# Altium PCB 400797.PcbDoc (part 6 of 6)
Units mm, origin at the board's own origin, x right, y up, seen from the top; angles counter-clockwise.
Board outline 155 x 63.5 mm, 4 copper layers (Top Layer, Mid-Layer 1, Mid-Layer 2, Bottom Layer), stack 1.514 mm thick; 317 components, 286 nets, 1519 pads, 2174 vias.
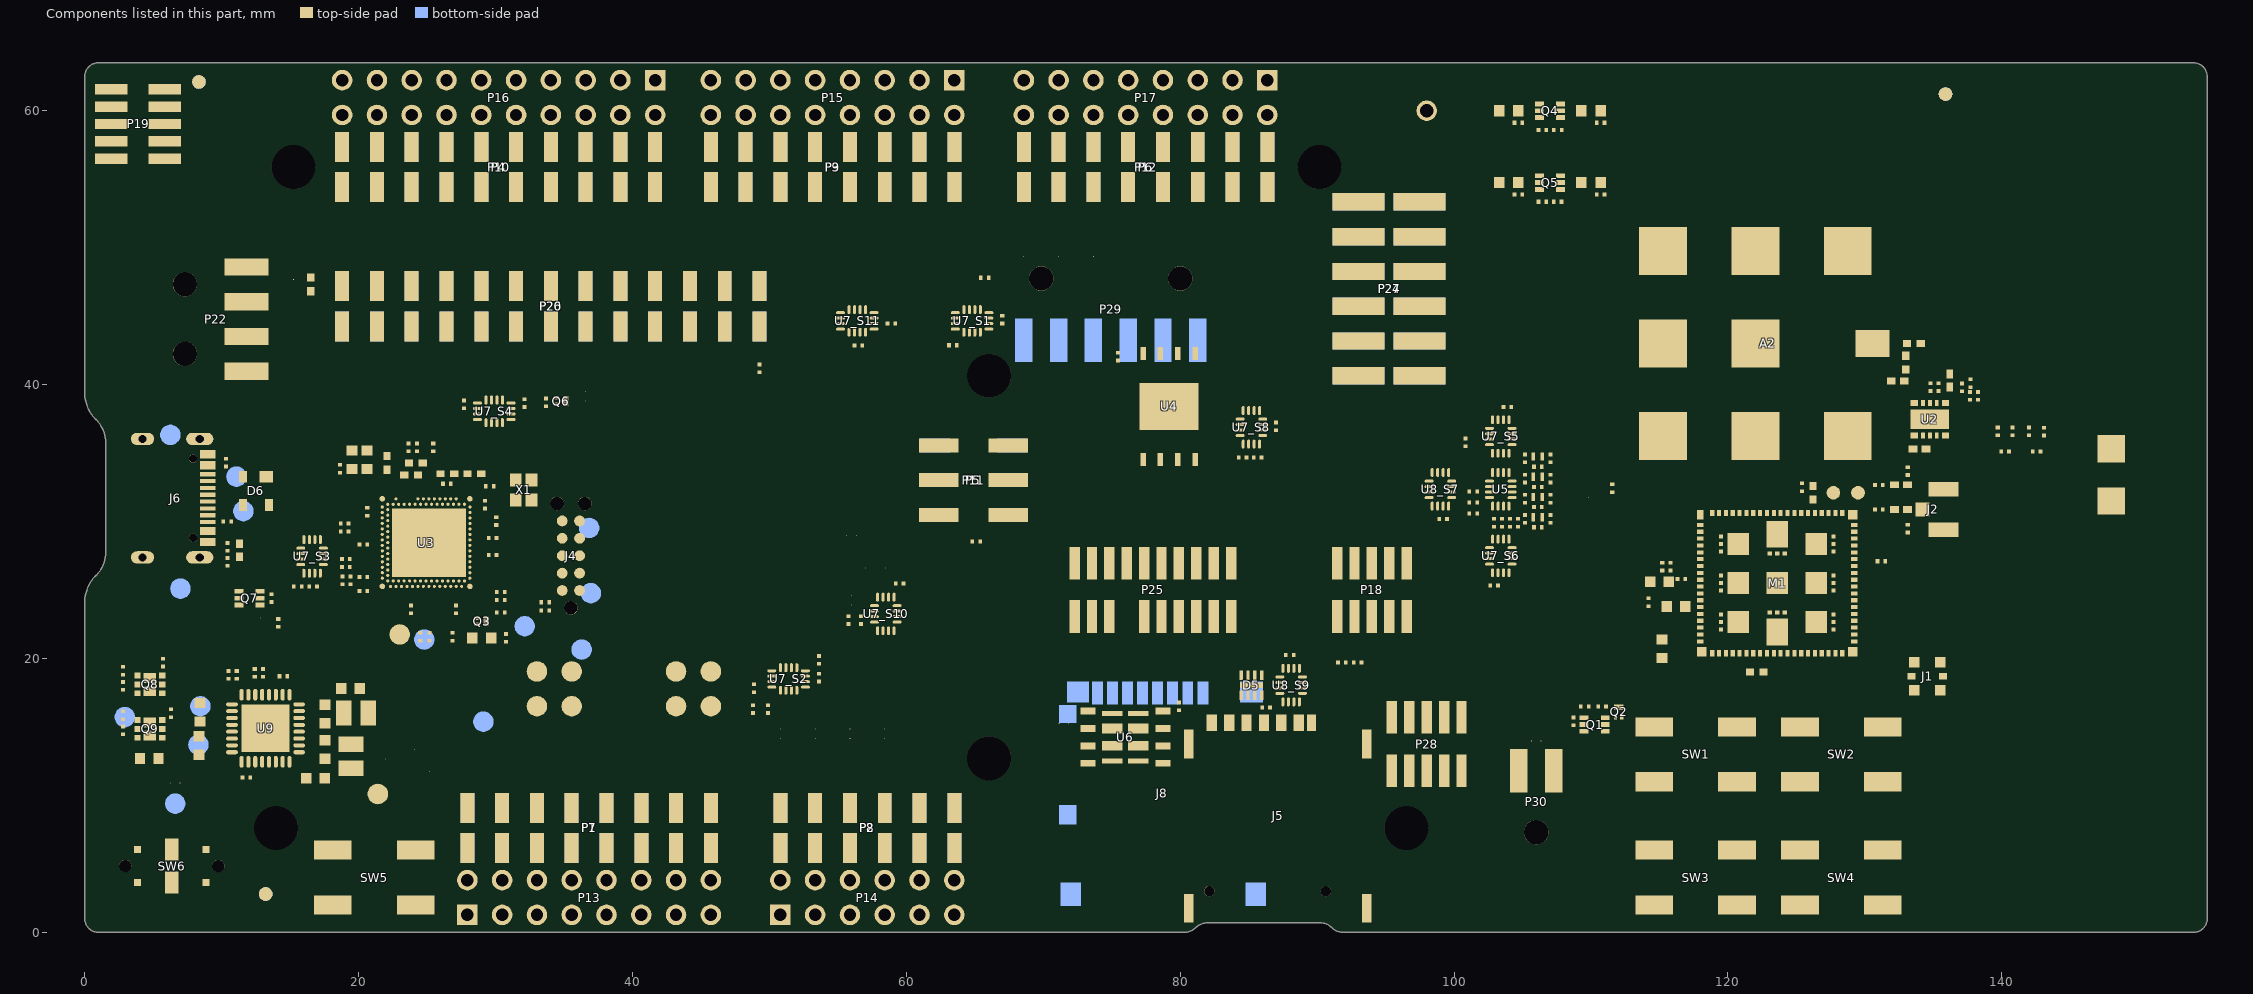
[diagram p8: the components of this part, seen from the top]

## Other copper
Top Layer:
  rectangle net GND: 141.732,30.087 142.85,34.416
  rectangle net GND: 141.732,36.867 142.85,38.837
  region net VIN_5V': 39.626,46.225 38.606,46.225 38.606,45.225 39.626,45.225
  region net VDD_nRF: 42.166,46.225 41.146,46.225 41.146,45.225 42.166,45.225
  region net VDD_nRF: 111.048,31.745 111.05,31.747 111.05,31.89 cw(c111.256,31.89) 111.11,32.035 111.307,32.232 cw(c111.41,32.129) 111.41,32.275 111.679,32.275 cw(c111.679,32.104) 111.8,32.225 112.007,32.018 cw(c111.906,31.916) 112.049,31.916 112.049,31.742
  region net VDD_5V: 43.446,42.581 44.946,42.581 cw(c44.946,42.256) 45.271,42.256 cw(c44.946,42.256) 44.946,41.931 43.446,41.931 cw(c43.446,42.256) 43.121,42.256 cw(c43.446,42.256)
  region net VDD: 71.375,20.85 70.5,20.85 ccw(c70.5,20.35) 70,20.35 ccw(c70.5,20.35) 70.5,19.85 71.375,19.85
  region net VDD: 71.125,20.85 72,20.85 cw(c72,20.35) 72.5,20.35 cw(c72,20.35) 72,19.85 71.125,19.85
  region net VDD: 22.558,39.485 23.177,38.866 ccw(c23.53,39.22) 23.884,38.866 ccw(c23.53,39.22) 23.884,39.573 23.265,40.192
  region net VDD: 22.735,39.308 22.116,39.927 cw(c22.47,40.28) 22.116,40.634 cw(c22.47,40.28) 22.823,40.634 23.442,40.015
  region net VDD_5V: 16.144,38.66 16.144,36.749 cw(c15.819,36.751) 15.494,36.751 15.494,38.66 cw(c15.819,38.66) 15.819,38.985 cw(c15.819,38.66)
  region net VIN_5V': 3.62,15.29 3.62,16.195 cw(c4,16.195) 4,16.575 5.5,16.575 cw(c5.5,16.25) 5.825,16.25 cw(c5.5,16.25) 5.5,15.925 4.285,15.925 ccw(c4.285,15.71) 4.07,15.71 4.07,15.29
  region net GND: 18.025,10.85 17.25,10.85 17.25,11.425 16.825,11.85 16.3,11.85 16.2,11.95 16.2,13.275 15.975,13.5 15.65,13.5 15.65,13.8 16.175,13.8 16.925,13.05 18.025,13.05
  region net GND: 15.65,15.5 16.2,15.5 16.95,16.25 18.025,16.25 18.025,17.025 18.4,17.4 19.1,17.4 19.1,18.2 17.5,18.2 17.15,17.85 17.15,16.975 15.975,15.8 15.65,15.8
  pour cut-out: 16.201,16.024 17.138,16.962 17.05,17.05 16.113,16.113
  pour cut-out: 17.025,17.85 17.025,17 17.15,17 17.15,17.85
  pour cut-out: 17.163,17.862 17.513,18.212 17.425,18.3 17.075,17.95
  pour cut-out: 19.1,18.325 17.5,18.325 17.5,18.2 19.1,18.2
  pour cut-out: 140.004,36.799 140.075,36.752 140.138,36.739 140.269,36.652 140.356,36.521 140.387,36.367 140.387,35.867 140.356,35.713 140.292,35.617 140.309,35.591 140.368,35.552 140.456,35.421 140.486,35.267 140.486,34.967 140.456,34.813 140.368,34.682 140.31,34.643 140.269,34.582 140.138,34.495 139.984,34.464 139.384,34.464 139.23,34.495 139.099,34.582 139.012,34.713 138.982,34.867 138.982,35.367 139.012,35.521 139.074,35.614 138.984,35.614 138.864,35.638 138.76,35.595 138.667,35.524 138.596,35.431 138.551,35.323 138.531,35.171 138.531,20.319 138.535,20.3 138.531,20.28 138.533,20.261 138.501,19.938 138.49,19.9 138.486,19.861 138.392,19.551 138.373,19.516 138.362,19.478 138.209,19.193 138.184,19.162 138.165,19.127 137.96,18.877 137.929,18.851 137.904,18.821 137.654,18.615 137.619,18.597 137.588,18.572 137.303,18.419 137.265,18.407 137.23,18.389 136.92,18.295 136.88,18.291 136.842,18.279 136.52,18.248 136.5,18.249 136.481,18.246 136.461,18.249 136.345,18.249 136.288,18.165 136.158,18.078 136.004,18.047 135.424,18.047 135.27,18.078 135.139,18.165 135.052,18.296 135.021,18.45 135.021,18.95 135.052,19.104 135.139,19.235 135.27,19.322 135.424,19.353 136.004,19.353 136.158,19.322 136.288,19.235 136.336,19.163 136.449,19.163 136.702,19.188 136.915,19.252 137.111,19.357 137.282,19.498 137.423,19.67 137.528,19.866 137.593,20.079 137.618,20.332 137.618,35.186 137.613,35.207 137.619,35.233 137.617,35.26 137.65,35.51 137.667,35.56 137.677,35.612 137.774,35.845 137.803,35.889 137.826,35.936 137.98,36.137 138.02,36.172 138.055,36.211 138.255,36.365 138.302,36.388 138.346,36.418 138.58,36.514 138.631,36.525 138.681,36.542 138.778,36.554 138.83,36.589 138.984,36.62 139.078,36.62 139.099,36.652 139.23,36.739 139.338,36.761 139.396,36.799 139.55,36.83 139.85,36.83
  pour cut-out: 30.6,22 30.1,22 30.1,21 30.6,21
  pour cut-out: 29.2,22 28.7,22 28.7,21 29.2,21
  region net VSYS: 16.613,14.511 17.229,13.895 17.229,13.7 17.938,13.7 17.938,15.6 17.229,15.6 17.229,15.427 16.613,14.811
  pour cut-out: 19.6,18.3 19.1,18.3 19.1,17.3 19.6,17.3
  pour cut-out: 8.7,13.4 8.7,13.9 7.7,13.9 7.7,13.4
  region net 5V: 38.61,3.811 38.61,10.2 37.59,10.2 37.59,3.811
  region net VDD_5V: 8,13.95 8,14.8 6.45,14.8 6.05,14.4 5.4,14.4 5.4,13.95
  region net VDD_5V: 6.4,11.4 6.1,11.4 5.9,11.6 5.9,14.4 5.4,14.4 5.4,13.8 5.1,13.8 5.1,10.7 5.4,10.4 6.4,10.4
  region net VBUS': 10.3,26.9 11,26.9 11,27.7 11.6,27.7 11.6,26.7 11.2,26.3 10.3,26.3
  region net VDD_5V: 7.9,14.8 7.9,13.95 9.45,13.95 10,14.5 10.75,14.5 10.75,14.8
  region net VSYS: 7.95,15 7.95,15.95 9.75,15.95 10.4,15.3 10.8,15.3 10.8,15
  pour cut-out: 20.664,12.575 20.664,15.015 18.575,15.015 18.575,12.575
  region net VDD_3V0: 20.1,15.058 20.1,16.893 19.675,17.318 19.675,18.293 20.45,18.293 21.2,17.542 21.2,15.058
  region net VDD_1V8: 18.175,10.6 17.1,10.6 16.9,10.8 16.904,10.804 16.904,11.396 16.65,11.65 15.9,11.65 15.9,10.5 16.25,10.15 19.643,10.15 20.41,10.917 20.41,12.575 18.575,12.575 18.575,11
  pour cut-out: 126.154,20.972 126.285,20.885 126.372,20.754 126.403,20.6 126.403,20.15 126.372,19.996 126.356,19.972 126.356,19.718 126.369,19.614 126.404,19.531 126.469,19.446 126.634,19.319 126.842,19.233 127.058,19.204 127.066,19.206 132.8,19.206 132.819,19.235 132.95,19.322 133.104,19.353 133.684,19.353 133.838,19.322 133.968,19.235 134.056,19.104 134.086,18.95 134.086,18.45 134.056,18.296 133.968,18.165 133.838,18.078 133.684,18.047 133.104,18.047 132.95,18.078 132.819,18.165 132.8,18.194 127.09,18.194 127.066,18.189 127.04,18.195 127.013,18.193 126.632,18.243 126.582,18.26 126.53,18.27 126.175,18.418 126.131,18.447 126.084,18.47 125.779,18.704 125.761,18.724 125.739,18.739 125.715,18.775 125.707,18.782 125.684,18.812 125.675,18.822 125.674,18.825 125.555,18.98 125.532,19.027 125.503,19.071 125.407,19.302 125.397,19.353 125.38,19.403 125.347,19.651 125.349,19.677 125.344,19.703 125.344,19.705 125.344,19.972 125.328,19.996 125.297,20.15 125.297,20.6 125.328,20.754 125.415,20.885 125.546,20.972 125.7,21.003 126,21.003
  pour cut-out: 133.434,29.702 133.565,29.615 133.652,29.484 133.683,29.33 133.683,29.06 133.652,28.906 133.643,28.892 133.643,28.132 133.642,28.131 133.642,22.85 133.638,22.83 133.64,22.811 133.607,22.478 133.596,22.44 133.592,22.401 133.495,22.081 133.476,22.046 133.465,22.008 133.308,21.714 133.282,21.683 133.264,21.648 133.052,21.39 133.021,21.365 132.996,21.334 132.738,21.122 132.703,21.104 132.672,21.078 132.378,20.921 132.34,20.91 132.305,20.891 131.985,20.794 131.946,20.79 131.908,20.779 131.575,20.746 131.556,20.748 131.536,20.744 129.628,20.744 129.604,20.728 129.45,20.697 129,20.697 128.846,20.728 128.715,20.815 128.628,20.946 128.597,21.1 128.597,21.4 128.628,21.554 128.715,21.685 128.846,21.772 129,21.803 129.45,21.803 129.604,21.772 129.609,21.769 131.536,21.769 131.539,21.768 131.747,21.789 131.95,21.85 132.137,21.95 132.301,22.085 132.436,22.249 132.536,22.436 132.597,22.639 132.618,22.847 132.617,22.85 132.617,28.131 132.617,28.132 132.617,28.892 132.608,28.906 132.577,29.06 132.577,29.33 132.608,29.484 132.695,29.615 132.826,29.702 132.98,29.733 133.28,29.733
  region net VDD_5V: 44.706,47.075 44.706,42.956 45.222,42.44 43.17,42.44 43.686,42.956 43.686,47.075
  pour cut-out: 30.792,34.199 30.792,30.466 33.104,30.466 33.104,34.199
  pour cut-out: 134.507,1.667 142.284,1.667 142.284,0.001 134.507,0.001
Mid-Layer 1:
  pour cut-out: 131.28,31.205 132.395,31.205 cw(c132.395,31.045) 132.555,31.045 132.555,30.73 cw(c132.38,30.73) 132.38,30.555 131.295,30.555 cw(c131.295,30.747) 131.102,30.748 131.102,31.027 cw(c131.28,31.027)
  pour cut-out: 7.225,11.175 7.225,10.625 cw(c6.875,10.625) 6.875,10.275 6.3,10.275 cw(c6.3,10.625) 5.95,10.625 5.95,11.175 cw(c6.3,11.175) 6.3,11.525 6.875,11.525 cw(c6.875,11.175)
  pour cut-out: 84.625,29.525 84.625,28.975 cw(c84.275,28.975) 84.275,28.625 83.7,28.625 cw(c83.7,28.975) 83.35,28.975 83.35,29.525 cw(c83.7,29.525) 83.7,29.875 84.275,29.875 cw(c84.275,29.525)
  pour cut-out: 72.125,15.525 72.125,14.975 cw(c71.775,14.975) 71.775,14.625 71.2,14.625 cw(c71.2,14.975) 70.85,14.975 70.85,15.525 cw(c71.2,15.525) 71.2,15.875 71.775,15.875 cw(c71.775,15.525)
  pour cut-out: 72.125,13.525 72.125,12.975 cw(c71.775,12.975) 71.775,12.625 71.2,12.625 cw(c71.2,12.975) 70.85,12.975 70.85,13.525 cw(c71.2,13.525) 71.2,13.875 71.775,13.875 cw(c71.775,13.525)
  pour cut-out: 106.625,14.25 106.625,13.7 cw(c106.275,13.7) 106.275,13.35 105.7,13.35 cw(c105.7,13.7) 105.35,13.7 105.35,14.25 cw(c105.7,14.25) 105.7,14.6 106.275,14.6 cw(c106.275,14.25)
  pour cut-out: 56.275,29.856 55.725,29.856 cw(c55.725,30.206) 55.375,30.206 55.375,30.781 cw(c55.725,30.781) 55.725,31.131 56.275,31.131 cw(c56.275,30.781) 56.625,30.781 56.625,30.206 cw(c56.275,30.206)
  pour cut-out: 56.625,32.256 56.625,31.706 cw(c56.275,31.706) 56.275,31.356 55.7,31.356 cw(c55.7,31.706) 55.35,31.706 55.35,32.256 cw(c55.7,32.256) 55.7,32.606 56.275,32.606 cw(c56.275,32.256)
  pour cut-out: 56.625,29.256 56.625,28.706 cw(c56.275,28.706) 56.275,28.356 55.7,28.356 cw(c55.7,28.706) 55.35,28.706 55.35,29.256 cw(c55.7,29.256) 55.7,29.606 56.275,29.606 cw(c56.275,29.256)
  pour cut-out: 67.625,26.525 67.625,25.975 cw(c67.275,25.975) 67.275,25.625 66.7,25.625 cw(c66.7,25.975) 66.35,25.975 66.35,26.525 cw(c66.7,26.525) 66.7,26.875 67.275,26.875 cw(c67.275,26.525)
  pour cut-out: 67.625,28.025 67.625,27.475 cw(c67.275,27.475) 67.275,27.125 66.7,27.125 cw(c66.7,27.475) 66.35,27.475 66.35,28.025 cw(c66.7,28.025) 66.7,28.375 67.275,28.375 cw(c67.275,28.025)
  pour cut-out: 58.775,25.625 58.225,25.625 cw(c58.225,25.975) 57.875,25.975 57.875,26.55 cw(c58.225,26.55) 58.225,26.9 58.775,26.9 cw(c58.775,26.55) 59.125,26.55 59.125,25.975 cw(c58.775,25.975)
  pour cut-out: 57.275,25.625 56.725,25.625 cw(c56.725,25.975) 56.375,25.975 56.375,26.55 cw(c56.725,26.55) 56.725,26.9 57.275,26.9 cw(c57.275,26.55) 57.625,26.55 57.625,25.975 cw(c57.275,25.975)
  pour cut-out: 56.275,23.625 55.725,23.625 cw(c55.725,23.975) 55.375,23.975 55.375,24.55 cw(c55.725,24.55) 55.725,24.9 56.275,24.9 cw(c56.275,24.55) 56.625,24.55 56.625,23.975 cw(c56.275,23.975)
  pour cut-out: 58.725,20.875 59.275,20.875 cw(c59.275,20.525) 59.625,20.525 59.625,19.95 cw(c59.275,19.95) 59.275,19.6 58.725,19.6 cw(c58.725,19.95) 58.375,19.95 58.375,20.525 cw(c58.725,20.525)
  pour cut-out: 57.775,19.625 57.225,19.625 cw(c57.225,19.975) 56.875,19.975 56.875,20.55 cw(c57.225,20.55) 57.225,20.9 57.775,20.9 cw(c57.775,20.55) 58.125,20.55 58.125,19.975 cw(c57.775,19.975)
  pour cut-out: 58.145,15.125 58.695,15.125 cw(c58.695,14.775) 59.045,14.775 59.045,14.2 cw(c58.695,14.2) 58.695,13.85 58.145,13.85 cw(c58.145,14.2) 57.795,14.2 57.795,14.775 cw(c58.145,14.775)
  pour cut-out: 56.155,13.875 55.605,13.875 cw(c55.605,14.225) 55.255,14.225 55.255,14.8 cw(c55.605,14.8) 55.605,15.15 56.155,15.15 cw(c56.155,14.8) 56.505,14.8 56.505,14.225 cw(c56.155,14.225)
  pour cut-out: 53.065,15.125 53.615,15.125 cw(c53.615,14.775) 53.965,14.775 53.965,14.2 cw(c53.615,14.2) 53.615,13.85 53.065,13.85 cw(c53.065,14.2) 52.715,14.2 52.715,14.775 cw(c53.065,14.775)
  pour cut-out: 51.075,13.875 50.525,13.875 cw(c50.525,14.225) 50.175,14.225 50.175,14.8 cw(c50.525,14.8) 50.525,15.15 51.075,15.15 cw(c51.075,14.8) 51.425,14.8 51.425,14.225 cw(c51.075,14.225)
  pour cut-out: 24.925,12.725 25.475,12.725 cw(c25.475,12.375) 25.825,12.375 25.825,11.8 cw(c25.475,11.8) 25.475,11.45 24.925,11.45 cw(c24.925,11.8) 24.575,11.8 24.575,12.375 cw(c24.925,12.375)
  pour cut-out: 23.475,13.425 23.475,13.975 cw(c23.825,13.975) 23.825,14.325 24.4,14.325 cw(c24.4,13.975) 24.75,13.975 24.75,13.425 cw(c24.4,13.425) 24.4,13.075 23.825,13.075 cw(c23.825,13.425)
  pour cut-out: 22.325,12.675 22.325,12.125 cw(c21.975,12.125) 21.975,11.775 21.4,11.775 cw(c21.4,12.125) 21.05,12.125 21.05,12.675 cw(c21.4,12.675) 21.4,13.025 21.975,13.025 cw(c21.975,12.675)
  pour cut-out: 9.125,56.975 9.125,57.525 cw(c9.475,57.525) 9.475,57.875 10.05,57.875 cw(c10.05,57.525) 10.4,57.525 10.4,56.975 cw(c10.05,56.975) 10.05,56.625 9.475,56.625 cw(c9.475,56.975)
  pour cut-out: 9.125,58.82 9.125,59.37 cw(c9.475,59.37) 9.475,59.72 10.05,59.72 cw(c10.05,59.37) 10.4,59.37 10.4,58.82 cw(c10.05,58.82) 10.05,58.47 9.475,58.47 cw(c9.475,58.82)
  pour cut-out: 15.515,46.694 14.965,46.694 cw(c14.965,47.044) 14.615,47.044 14.615,47.619 cw(c14.965,47.619) 14.965,47.969 15.515,47.969 cw(c15.515,47.619) 15.865,47.619 15.865,47.044 cw(c15.515,47.044)
  pour cut-out: 19.791,39.773 20.341,39.773 cw(c20.341,39.423) 20.691,39.423 20.691,38.848 cw(c20.341,38.848) 20.341,38.498 19.791,38.498 cw(c19.791,38.848) 19.441,38.848 19.441,39.423 cw(c19.791,39.423)
  pour cut-out: 36.3,39.787 36.85,39.787 cw(c36.85,39.437) 37.2,39.437 37.2,38.862 cw(c36.85,38.862) 36.85,38.512 36.3,38.512 cw(c36.3,38.862) 35.95,38.862 35.95,39.438 cw(c36.3,39.438)
  pour cut-out: 73.935,41.58 73.385,41.58 cw(c73.385,41.93) 73.035,41.93 73.035,42.505 cw(c73.385,42.505) 73.385,42.855 73.935,42.855 cw(c73.935,42.505) 74.285,42.505 74.285,41.93 cw(c73.935,41.93)
  pour cut-out: 73.385,49.625 73.935,49.625 cw(c73.935,49.275) 74.285,49.275 74.285,48.7 cw(c73.935,48.7) 73.935,48.35 73.385,48.35 cw(c73.385,48.7) 73.035,48.7 73.035,49.275 cw(c73.385,49.275)
  pour cut-out: 70.845,49.625 71.395,49.625 cw(c71.395,49.275) 71.745,49.275 71.745,48.7 cw(c71.395,48.7) 71.395,48.35 70.845,48.35 cw(c70.845,48.7) 70.495,48.7 70.495,49.275 cw(c70.845,49.275)
  pour cut-out: 68.305,49.625 68.855,49.625 cw(c68.855,49.275) 69.205,49.275 69.205,48.7 cw(c68.855,48.7) 68.855,48.35 68.305,48.35 cw(c68.305,48.7) 67.955,48.7 67.955,49.275 cw(c68.305,49.275)
  pour cut-out: 104.098,51.076 104.098,50.526 cw(c103.748,50.526) 103.748,50.176 103.173,50.176 cw(c103.173,50.526) 102.823,50.526 102.823,51.076 cw(c103.172,51.076) 103.173,51.426 103.748,51.426 cw(c103.748,51.076)
  pour cut-out: 110.075,28.563 109.525,28.563 cw(c109.525,28.913) 109.175,28.913 109.175,29.488 cw(c109.525,29.488) 109.525,29.838 110.075,29.838 cw(c110.075,29.488) 110.425,29.488 110.425,28.912 cw(c110.075,28.912)
  pour cut-out: 110.075,30.75 109.525,30.75 cw(c109.525,31.1) 109.175,31.1 109.175,31.675 cw(c109.525,31.675) 109.525,32.025 110.075,32.025 cw(c110.075,31.675) 110.425,31.675 110.425,31.1 cw(c110.075,31.1)
  pour cut-out: 135.647,36.572 136.128,36.572 cw(c136.128,36.475) 136.225,36.475 136.225,36.075 cw(c136.122,36.075) 136.122,35.972 135.653,35.972 cw(c135.653,36.075) 135.55,36.075 135.55,36.475 cw(c135.647,36.475)
  pour cut-out: 134.175,35.625 134.775,35.625 cw(c134.775,35.525) 134.875,35.525 134.875,35.075 cw(c134.775,35.075) 134.775,34.975 134.175,34.975 cw(c134.175,35.075) 134.075,35.075 134.075,35.525 cw(c134.175,35.525)
  pour cut-out: 133.225,35.625 133.825,35.625 cw(c133.825,35.525) 133.925,35.525 133.925,35.075 cw(c133.825,35.075) 133.825,34.975 133.225,34.975 cw(c133.225,35.075) 133.125,35.075 133.125,35.525 cw(c133.225,35.525)
  pour cut-out: 133.787,18.357 133,18.357 133,19.043 133.787,19.043
  pour cut-out: 135,17.301 134.1,17.306 134.1,18.1 133.1,18.1 133.103,19.3 134.1,19.3 134.1,20.1 135,20.1 135,19.3 136,19.3 136,18.1 135,18.1
  pour cut-out: 135.32,19.043 136.107,19.043 136.107,18.357 135.32,18.357
  pour cut-out: 11.825,21.6 11.825,23.6 13.825,23.6 13.825,21.6
  pour cut-out: 133.3,39.925 132.5,39.925 132.5,40.575 133.3,40.575
  pour cut-out: 133.325,41.5 133.325,40.7 132.675,40.7 132.675,41.5
  pour cut-out: 133.325,42.5 133.325,41.7 132.675,41.7 132.675,42.5
  pour cut-out: 133.5,42.675 132.7,42.675 132.7,43.325 133.5,43.325
  pour cut-out: 133.264,38.947 133.939,38.947 133.939,38.347 133.264,38.347
  pour cut-out: 133.505,31.555 137.03,31.555 137.03,30.23 133.505,30.23
  pour cut-out: 131.102,33.005 132.555,33.005 132.555,32.355 131.102,32.355
  pour cut-out: 132.705,33.005 133.505,33.005 133.505,32.355 132.705,32.355
  pour cut-out: 132.705,31.205 133.505,31.205 133.505,30.555 132.705,30.555
  pour cut-out: 133.355,29.978 133.355,29.553 132.905,29.553 132.905,29.978
  pour cut-out: 133.355,29.408 133.355,28.983 132.905,28.983 132.905,29.408
  pour cut-out: 132.905,33.753 132.905,34.178 133.355,34.178 133.355,33.753
  pour cut-out: 132.905,33.183 132.905,33.608 133.355,33.608 133.355,33.183
  pour cut-out: 134.507,1.667 142.284,1.667 142.284,0.001 134.507,0.001
Mid-Layer 2:
  region net VDD_nRF: 111,32.2 112.1,32.2 cw(c112.1,32) 112.3,32 112.3,31.4 110.8,31.4 110.8,32 cw(c111,32)
  region net VDD_5V: 15.494,36.75 15.494,38.25 cw(c15.819,38.25) 15.819,38.575 cw(c15.819,38.25) 16.144,38.25 16.144,36.75 cw(c15.819,36.75) 15.819,36.425 cw(c15.819,36.75)
  region net VIN_5V': 38.791,44.221 38.791,45.721 cw(c39.116,45.721) 39.116,46.046 cw(c39.116,45.721) 39.441,45.721 39.441,44.221 cw(c39.116,44.221) 39.116,43.896 cw(c39.116,44.221)
  region net VDD_5V: 43.446,42.581 44.946,42.581 cw(c44.946,42.256) 45.271,42.256 cw(c44.946,42.256) 44.946,41.931 43.446,41.931 cw(c43.446,42.256) 43.121,42.256 cw(c43.446,42.256)
  region net VDD: 23.301,38.99 22.24,40.051 cw(c22.47,40.28) 22.24,40.51 cw(c22.47,40.28) 22.699,40.51 23.76,39.449 cw(c23.53,39.22) 23.76,38.99 cw(c23.53,39.22)
  region net VDD: 71.375,20.85 70.5,20.85 ccw(c70.5,20.35) 70,20.35 ccw(c70.5,20.35) 70.5,19.85 71.375,19.85
  region net VDD: 71.125,20.85 72,20.85 cw(c72,20.35) 72.5,20.35 cw(c72,20.35) 72,19.85 71.125,19.85
  region net 5V: 66.972,35.236 68.472,35.236 ccw(c68.472,35.561) 68.797,35.561 ccw(c68.472,35.561) 68.472,35.886 66.972,35.886 ccw(c66.972,35.561) 66.647,35.561 ccw(c66.972,35.561)
  region net VIN_5V': 14.719,36.75 14.719,38.25 cw(c15.044,38.25) 15.044,38.575 cw(c15.044,38.25) 15.369,38.25 15.369,36.75 cw(c15.044,36.75) 15.044,36.425 cw(c15.044,36.75)
  region net VDD: 22.411,38.439 22.723,38.752 cw(c23.068,38.406) 23.068,38.895 23.595,38.895 22.145,40.345 22.145,39.793 cw(c21.717,39.793) 22.019,39.491 21.689,39.161
  pour cut-out: 134.507,1.667 142.284,1.667 142.284,0.001 134.507,0.001
Bottom Layer:
  rectangle net GND: 141.834,30.325 142.951,38.812
  rectangle net VIN_5V': 38.606,45.225 39.626,46.225
  rectangle net VDD_nRF: 41.146,45.225 42.166,46.225
  region net VDD_nRF: 112.1,31.3 111,31.3 cw(c111,31.5) 110.8,31.5 110.8,32.8 111.782,32.8 112.3,32.282 112.3,31.5 cw(c112.1,31.5)
  region net 5V: 55.425,20.5 55.425,22 cw(c55.75,22) 55.75,22.325 cw(c55.75,22) 56.075,22 56.075,20.5 cw(c55.75,20.5) 55.75,20.175 cw(c55.75,20.5)
  region net VDD_5V: 43.446,42.581 44.946,42.581 cw(c44.946,42.256) 45.271,42.256 cw(c44.946,42.256) 44.946,41.931 43.446,41.931 cw(c43.446,42.256) 43.121,42.256 cw(c43.446,42.256)
  region net VDD: 22.735,39.308 22.116,39.927 cw(c22.47,40.28) 22.116,40.634 cw(c22.47,40.28) 22.823,40.634 23.442,40.015
  region net VDD: 22.558,39.485 23.177,38.866 ccw(c23.53,39.22) 23.884,38.866 ccw(c23.53,39.22) 23.884,39.573 23.265,40.192
  region net VIN_5V': 14.719,36.75 14.719,38.25 cw(c15.044,38.25) 15.044,38.575 cw(c15.044,38.25) 15.369,38.25 15.369,36.75 cw(c15.044,36.75) 15.044,36.425 cw(c15.044,36.75)
  region net VDD_5V: 16.144,38.25 16.144,36.75 cw(c15.819,36.75) 15.819,36.425 cw(c15.819,36.75) 15.494,36.75 15.494,38.25 cw(c15.819,38.25) 15.819,38.575 cw(c15.819,38.25)
  region net VIN_5V': 4,16.575 5.5,16.575 cw(c5.5,16.25) 5.825,16.25 cw(c5.5,16.25) 5.5,15.925 4,15.925 cw(c4,16.25) 3.675,16.25 cw(c4,16.25)
  region net 5V: 37.59,3.811 37.59,9.3 38.61,9.3 38.61,3.811
  region net VSYS: 17.9,14.3 17.9,15.3 15.7,17.5 10.7,17.5 8.8,15.6 8.8,14.9 10.3,14.9 10.3,15.8 11.1,16.6 15.4,16.6 16.6,15.4 16.6,14.3
  region net VDD_5V: 43.686,47.075 43.686,42.956 43.17,42.44 45.222,42.44 44.706,42.956 44.706,47.075
  region: 147.207,48.236 147.207,48.998 147.735,48.998 147.735,48.236
  pour cut-out: 134.507,1.667 142.284,1.667 142.284,0.001 134.507,0.001
Multi-Layer:
  pour cut-out: 142.284,51.067 138.063,51.067 138.063,63.501 142.284,63.501

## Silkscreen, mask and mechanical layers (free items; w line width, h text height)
Top Overlay:
  circle w0.254: c88.113,54.367 r0.127
  circle w0.254: c65.278,54.357 r0.127
  circle w0.254: c43.434,54.357 r0.127
  circle w0.254: c26.162,9.145 r0.127
  circle w0.254: c49.022,9.145 r0.127
  region: 78.374,9.074 78.374,8.33 73.156,8.362 74.122,9.329 78.119,9.329
  region: 78.296,3.108 78.296,2.248 78.119,2.071 73.281,2.071 73.104,2.248 73.174,2.318 73.174,3.13 78.274,3.13
  lines w0.1: 9.7,19.5 7.6,19.5 7.6,10.7 20.4,10.7 ; 13.7,19.5 21.6,19.5 21.6,13.3 ; 21.6,11 21.6,11.4 ; 18.1,32.8 19.7,32.8 19.7,22.8 27.9,22.8 27.9,24.6 29.7,24.6 29.7,27 30.7,27 30.7,30.4 33.3,30.4 33.3,34.8 22.7,34.8 22.7,35.9 18.1,35.9 18.1,32.8
  lines w0.15: 37.084,17.78 41.656,17.78 ; 39.37,15.494 39.37,20.066 ; 37.084,15.494 37.084,20.066 41.656,20.066 41.656,15.494 37.084,15.494
  lines w0.25: 73.104,8.237 73.104,2.248 ccw(c73.281,2.248) 73.281,2.071 78.119,2.071 ccw(c78.119,2.248) 78.296,2.248 78.296,9.152 ccw(c78.119,9.152) 78.119,9.329 74.195,9.329 ; 73.155,8.362 74.07,9.277
  lines w0.254: 12.38,60.961 92.837,60.961 ; 14.224,62.231 17.018,62.231 ; 16.764,62.231 16.256,62.485 16.256,61.977 17.018,62.231 ; 26.67,2.541 67.996,2.541 ; 65.481,1.232 65.989,0.978 65.989,1.486 65.227,1.232 ; 68.021,1.232 65.227,1.232 ; 88.341,62.192 88.849,61.938 88.849,62.446 88.087,62.192 ; 90.881,62.192 88.087,62.192 ; 17.018,62.231 16.256,61.723 16.256,62.739 17.018,62.231 ; 65.227,1.232 65.989,0.724 65.989,1.74 65.227,1.232 ; 88.087,62.192 88.849,62.7 88.849,61.684 88.087,62.192
  text "'.PCBnumber'" at 138.776,61.712 h2.03
  text "GND" at 10.662,61.695 h1.78
  text "GND" at 91.198,61.656 h1.78
  text "'.PCBrevision'" at 138.855,60.492 h1.52
  text "GND" at 96.383,57.564 h1.78
  text "DEBUG OUT" at 0.418,53.688 h1.8
  text "'.Productname'" at 115.825,53.45 h3
  text "COEX1" at 99.601,52.949 h1.3
  text "COEX0" at 87.337,52.919 h1.3
  text "COEX2" at 87.421,50.484 h1.3
  text "P0.11" at 34.537,50.465 h1.7 r90
  text "P0.29" at 99.601,50.418 h1.3
  text "nRF CURRENT / MEASUREMENT" at 0.418,50.296 h1.8
  text "P0.21" at 86.861,50.189 h1.7 r90
  text "P0.31" at 19.297,50.168 h1.7 r90
  text "GND" at 26.928,50.111 h1.7 r90
  text "P0.12" at 31.997,50.096 h1.7 r90
  text "P0.01" at 61.461,50.076 h1.7 r90
  text "P0.13" at 29.457,50.066 h1.7 r90
  text "P0.10" at 37.077,49.986 h1.7 r90
  text "P0.27" at 71.621,49.856 h1.7 r90
  text "P0.22" at 84.321,49.82 h1.7 r90
  text "P0.25" at 76.701,49.774 h1.7 r90
  text "P0.23" at 81.781,49.79 h1.7 r90
  text "P0.28" at 69.081,49.756 h1.7 r90
  text "P0.26" at 74.161,49.747 h1.7 r90
  text "P0.07" at 46.221,49.743 h1.7 r90
  text "P0.24" at 79.241,49.741 h1.7 r90
  text "P0.20" at 24.377,49.71 h1.7 r90
  text "P0.02" at 58.921,49.707 h1.7 r90
  text "P0.30" at 21.837,49.689 h1.7 r90
  text "P0.03" at 56.381,49.677 h1.7 r90
  text "P0.09" at 39.617,49.653 h1.7 r90
  text "P0.08" at 42.157,49.643 h1.7 r90
  text "P0.05" at 51.301,49.661 h1.7 r90
  text "P0.06" at 48.761,49.634 h1.7 r90
  text "P0.04" at 53.841,49.628 h1.7 r90
  text "P0.00" at 64.001,49.597 h1.7 r90
  text "VDD_nRF" at 0.6,49.229 h1.4
  text "SDATA" at 87.421,47.944 h1.3
  text "SCLK" at 99.601,47.869 h1.3
  text "VDD_5V" at 0.6,46.689 h1.4
  text "VIO" at 89.07,45.413 h1.27
  text "GND" at 99.601,45.329 h1.3
  text "NC" at 0.6,44.149 h1.4
  text "MAGPIO0" at 85.869,42.864 h1.3
  text "MAGPIO1" at 99.601,42.789 h1.3
  text "ID" at 49.667,41.989 h1.3 r90
  text "GND" at 0.6,41.609 h1.4
  text "SEL" at 36.968,41.194 h1.3 r90
  text "VIO / REF" at 47.721,40.96 h1.3 r90
  text "VTG" at 24.268,40.743 h1.3 r90
  text "VDD" at 21.727,40.669 h1.3 r90
  text "VDD / nRF" at 42.625,40.581 h1.3 r90
  text "VDD / 5V" at 45.165,40.581 h1.3 r90
  text "VIN / 5V" at 40.094,40.49 h1.3 r90
  text "VDD / GPIO" at 19.765,40.383 h1.3 r90
  text "SWD / IO" at 27.416,40.341 h1.3 r90
  text "SWD / CLK" at 29.956,40.341 h1.3 r90
  text "MAGPIO2" at 85.953,40.324 h1.3
  text "SWO" at 31.888,40.312 h1.3 r90
  text "GND" at 99.601,40.249 h1.3
  text "RESET" at 34.428,39.933 h1.3 r90
  text "DEBUGGER" at 18.059,35.911 h1.8
  text "P0.12" at 57.761,35.103 h1.52
  text "5V" at 69.199,35.051 h1.52
  text "P0.11" at 69.197,32.589 h1.52
  text "P0.13" at 57.735,32.563 h1.52
  text "DETECT" at 69.197,30.091 h1.52
  text "RESET" at 57.107,30.02 h1.52
  text "TRACE" at 73.5,28.65 h1.8
  text "DEBUG IN" at 89.5,28.65 h1.8
  text "GPS" at 133.85,26.95 h1.8
  text "DEBUGGER" at 1.6,24.55 h1.8
  text "VCOM0" at 31.29,21.15 h1.8
  text "VCOM1" at 41.45,21.15 h1.8
  text "LTE" at 133.75,20.45 h1.8
  text "nPM1300" at 15.249,19.47 h1.8
  text "TxD" at 37.298,18.54 h1.27
  text "RxD" at 39.577,18.54 h1.27
  text "SIM / INTERFACE" at 93.685,17.35 h1.8
  text "MFF2 UICC" at 71.326,17.15 h1.8
  text "CTS" at 37.317,16.254 h1.27
  text "RTS" at 39.666,16.254 h1.27
  text "BUTTON 1" at 113.14,16.15 h1.8
  text "BUTTON 2" at 123.79,16.15 h1.8
  text "VDD" at 28.451,10.301 h1.7 r90
  text "VDD" at 30.991,10.301 h1.7 r90
  text "RESET" at 33.532,10.301 h1.7 r90
  text "VDD" at 36.071,10.301 h1.7 r90
  text "5V" at 38.601,10.301 h1.7 r90
  text "GND" at 41.152,10.301 h1.7 r90
  text "GND" at 43.692,10.301 h1.7 r90
  text "N.C." at 46.232,10.301 h1.7 r90
  text "P0.14" at 51.301,10.301 h1.7 r90
  text "P0.15" at 53.841,10.301 h1.7 r90
  text "P0.16" at 56.381,10.301 h1.7 r90
  text "P0.17" at 58.921,10.301 h1.7 r90
  text "P0.18" at 61.461,10.301 h1.7 r90
  text "P0.19" at 64.001,10.301 h1.7 r90
  text "POWER" at 1.85,7.15 h1.8
  text "RESET" at 16.636,7.15 h1.8
  text "BUTTON 3" at 113.14,7.15 h1.8
  text "BUTTON 4" at 123.79,7.15 h1.8
  text "NANO / SIM / CARD" at 78.2,2.95 h1.8 r90
  text "GND" at 68.338,0.696 h1.78
  text "OFF" at 0.75,0.65 h1.8
  text "ON" at 8.5,0.65 h1.8
  text "For evaluation only; / not FCC approved for resale." at 145.852,0.413 h1.52 r90
  text "SIM CURRENT / MEASUREMENT" at 111.8,0.25 h1.8 r90
Bottom Overlay:
  drawing of 357 lines, arcs and shapes, not listed
  text "IOEXP_SCL" at 111.914,62.501 h1.91 r180
  text "P0.31" at 106.351,62.417 h1.91 r180
  text "P0.19" at 122.935,62.418 h1.91 r180
  text "Button 4" at 128.443,62.41 h1.91 r180
  text "nRF91" at 139.306,60.613 h2.03 r180
  text "IOEXP_SDA" at 111.736,59.961 h1.91 r180
  text "P0.30" at 106.083,59.877 h1.91 r180
  text "P0.18" at 122.931,59.878 h1.91 r180
  text "Button 3" at 128.471,59.87 h1.91 r180
  text "IOEXP_IRQ" at 111.942,57.421 h1.91 r180
  text "P0.19" at 106.28,57.337 h1.91 r180
  text "P0.09" at 122.719,57.337 h1.91 r180
  text "Button 2" at 128.489,57.337 h1.91 r180
  text "I2C" at 144.164,56.773 h1.78 r180
  text "GPIO" at 106.02,54.787 h2.03 r180
  text "Function" at 112.795,54.784 h2.03 r180
  text "P0.08" at 122.721,54.797 h1.91 r180
  text "Button 1" at 128.696,54.797 h1.91 r180
  text "BC" at 146.638,54.572 h1.78 r180
  text "COEX1" at 99.601,53.723 h1.27 r180
  text "COEX0" at 87.418,53.694 h1.27 r180
  text "P0.28" at 69.063,53.323 h1.78 r90
  text "P0.26" at 74.143,53.322 h1.78 r90
  text "P0.25" at 76.683,53.305 h1.78 r90
  text "P0.24" at 79.223,53.318 h1.78 r90
  text "P0.23" at 81.763,53.304 h1.78 r90
  text "P0.22" at 84.303,53.294 h1.78 r90
  text "P0.27" at 71.603,53.271 h1.78 r90
  text "P0.31" at 19.283,53.155 h1.65 r90
  text "P0.30" at 21.823,53.155 h1.65 r90
  text "P0.20" at 24.363,53.155 h1.65 r90
  text "GND" at 26.914,53.155 h1.65 r90
  text "P0.13" at 29.443,53.155 h1.65 r90
  text "P0.12" at 31.983,53.155 h1.65 r90
  text "P0.11" at 34.523,53.155 h1.65 r90
  text "P0.10" at 37.063,53.155 h1.65 r90
  text "P0.09" at 39.603,53.156 h1.65 r90
  text "P0.08" at 42.143,53.155 h1.65 r90
  text "P0.07" at 46.207,53.155 h1.65 r90
  text "P0.06" at 48.747,53.155 h1.65 r90
  text "P0.05" at 51.287,53.155 h1.65 r90
  text "P0.04 (D4)" at 53.74,53.159 h1.65 r90
  text "P0.03 (D3)" at 56.28,53.159 h1.65 r90
  text "P0.02 (D2)" at 58.82,53.158 h1.65 r90
  text "P0.01 (D1)" at 61.36,53.158 h1.65 r90
  text "P0.00 (ARDUINO D0)" at 63.9,53.166 h1.65 r90
  text "P0.21" at 86.818,53.172 h1.78 r90
  text "PIN" at 136.916,52.759 h1.78 r180
  text "LED 4" at 129.466,52.259 h1.91 r180
  text "(SCL)" at 20.466,52.251 h1.65 r90
  text "(SDA)" at 23.006,52.251 h1.65 r90
  text "(AREF)" at 25.546,52.251 h1.65 r90
  text "(D13)" at 30.626,52.251 h1.65 r90
  text "(D12)" at 33.166,52.25 h1.65 r90
  text "(D11)" at 35.706,52.25 h1.65 r90
  text "(D10)" at 38.246,52.251 h1.65 r90
  text "(D9)" at 40.786,52.25 h1.65 r90
  text "(D8)" at 43.326,52.25 h1.65 r90
  text "(D7)" at 47.39,52.25 h1.65 r90
  text "(D6)" at 49.93,52.25 h1.65 r90
  text "(D5)" at 52.47,52.25 h1.65 r90
  text "P0.05" at 122.736,52.257 h1.91 r180
  text "EXP" at 141.027,51.467 h1.52 r180
  text "COEX2" at 87.5,51.259 h1.27 r180
  text "P0.29" at 99.601,51.176 h1.27 r180
  text "P0.04" at 122.724,49.717 h1.91 r180
  text "LED 3" at 129.493,49.717 h1.91 r180
  text "SDATA" at 87.5,48.719 h1.27 r180
  text "SCLK" at 99.601,48.643 h1.27 r180
  text "BC" at 144.681,48.195 h1.78 r180
  text "LED 2" at 129.51,47.179 h1.91 r180
  text "P0.01" at 122.958,47.177 h1.91 r180
  text "*" at 105.642,47.118 h2.54 r180
  text "VIO" at 89.07,46.179 h1.27 r180
  text "GND" at 99.601,46.103 h1.27 r180
  text "*" at 114.151,45.213 h2.54 r180
  text "*" at 140.44,44.705 h2.54 r180
  text "LED 1" at 129.717,44.639 h1.91 r180
  text "P0.00" at 122.683,44.637 h1.91 r180
  text "VDD" at 105.472,44.378 h1.45 r180
  text "MAGPIO0" at 85.983,43.639 h1.27 r180
  text "MAGPIO1" at 99.601,43.563 h1.27 r180
  text "VDD / GPIO" at 19.765,43.209 h1.4 r90
  text "SWD / IO" at 27.416,43.014 h1.4 r90
  text "SWD / CLK" at 29.956,43.014 h1.4 r90
  text "VIN / 5V" at 40.094,43.029 h1.4 r90
  text "VDD / nRF" at 42.625,43.014 h1.4 r90
  text "VDD / 5V" at 45.165,43.014 h1.4 r90
  text "VDD" at 21.756,43.008 h1.4 r90
  text "VTG" at 24.296,43.008 h1.4 r90
  text "SWO" at 31.916,43.008 h1.4 r90
  text "RESET" at 34.456,43.007 h1.4 r90
  text "SEL" at 36.996,42.993 h1.4 r90
  text "VIO / REF" at 47.721,43.012 h1.4 r90
  text "ID" at 49.696,43.008 h1.4 r90
  text "LED" at 107.743,42.086 h2.03 r180
  text "Button" at 114.759,42.084 h2.03 r180
  text "GPIO" at 122.657,42.087 h2.03 r180
  text "Function" at 128.543,42.084 h2.03 r180
  text "Circuit" at 140.456,42.087 h2.03 r180
  text "MAGPIO2" at 86.065,41.099 h1.27 r180
  text "GND" at 99.601,41.023 h1.27 r180
  text "CTS2" at 129.938,38.8 h1.91 r180
  text "P0.17" at 123,38.795 h1.91 r180
  text "nRF91" at 137.528,36.992 h2.03 r180
  text "RTS2" at 130.032,36.26 h1.91 r180
  text "P0.16" at 122.945,36.255 h1.91 r180
  text "TxD2" at 129.91,33.717 h1.91 r180
  text "P0.29" at 122.682,33.715 h1.91 r180
  text "RESET" at 88.634,31.217 h1.91 r180
  text "RESET" at 95.644,31.217 h1.91 r180
  text "P0.21" at 102.392,31.216 h1.91 r180
  text "RxD2" at 129.898,31.177 h1.91 r180
  text "P0.28" at 122.773,31.175 h1.91 r180
  text "PIN" at 137.044,31.043 h1.78 r180
  text "nRF91" at 111.227,30.114 h2.03 r180
  text "AREF" at 88.893,28.677 h1.91 r180
  text "P0.20" at 95.838,28.677 h1.91 r180
  text "RESET" at 101.93,28.676 h1.91 r180
  text "P0.15" at 122.949,28.636 h1.91 r180
  text "CTS1" at 130.145,28.641 h1.91 r180
  text "DEF." at 109.335,28.122 h1.52 r180
  text "ALT." at 115.661,28.122 h1.52 r180
  text "BC" at 142.736,27.178 h1.78 r180
  text "D6" at 89.846,26.137 h1.91 r180
  text "P0.06" at 95.795,26.137 h1.91 r180
  text "COEX2" at 101.53,26.136 h1.91 r180
  text "PIN" at 117.577,26.135 h1.78 r180
  text "P0.14" at 122.923,26.096 h1.91 r180
  text "RTS1" at 130.239,26.101 h1.91 r180
  text "BC" at 117.577,23.885 h1.78 r180
  text "D3" at 89.87,23.597 h1.91 r180
  text "P0.03" at 95.82,23.597 h1.91 r180
  text "COEX1" at 101.737,23.596 h1.91 r180
  text "P0.27" at 122.832,23.557 h1.91 r180
  text "TxD1" at 130.117,23.558 h1.91 r180
  text "IF / MCU" at 139.562,22.741 h1.4 r180
  text "ARDUINO" at 110.893,21.221 h1.52 r180
  text "D2" at 89.887,21.057 h1.91 r180
  text "P0.02" at 95.836,21.057 h1.91 r180
  text "COEX0" at 101.469,21.056 h1.91 r180
  text "P0.26" at 122.772,21.017 h1.91 r180
  text "RxD1" at 130.105,21.018 h1.91 r180
  text "Arduino" at 87.735,18.491 h2.03 r180
  text "Default" at 95.059,18.491 h2.03 r180
  text "Alt." at 102.813,18.491 h2.03 r180
  text "Circuit" at 111.353,18.491 h2.03 r180
  text "GPIO" at 122.657,18.466 h2.03 r180
  text "Function" at 128.543,18.463 h2.03 r180
  text "Circuit" at 140.456,18.466 h2.03 r180
  text "P0.14 (A0)" at 51.2,16.523 h1.65 r90
  text "P0.18 (A4)" at 61.36,16.474 h1.65 r90
  text "P0.16 (A2)" at 56.28,16.398 h1.65 r90
  text "P0.19 (A5)" at 63.9,16.405 h1.65 r90
  text "P0.17 (A3)" at 58.82,16.309 h1.65 r90
  text "P0.15 (A1)" at 53.74,16.112 h1.65 r90
  text "P0.20" at 122.763,15.301 h1.91 r180
  text "CS" at 130.786,15.306 h1.91 r180
  text "nRF91" at 139.052,14.924 h2.03 r180
  text "RESET" at 33.518,14.063 h1.65 r90
  text "GND" at 41.138,13.339 h1.65 r90
  text "GND" at 43.678,13.339 h1.65 r90
  text "VDD" at 28.437,13.162 h1.65 r90
  text "VDD" at 30.977,13.162 h1.65 r90
  text "VDD" at 36.057,13.162 h1.65 r90
  text "N.C." at 46.256,13.024 h1.78 r90
  text "P0.13" at 122.952,12.761 h1.91 r180
  text "SCK" at 130.187,12.766 h1.91 r180
  text "PIN" at 136.415,12.271 h1.78 r180
  text "5V" at 38.587,11.988 h1.65 r90
  text "BC" at 144.865,11.207 h1.78 r180
  text "P0.12" at 122.963,10.221 h1.91 r180
  text "MISO" at 129.74,10.226 h1.91 r180
  text "EXT MEMORY" at 138.41,7.873 h1.52 r180
  text "P0.11" at 123.074,7.681 h1.91 r180
  text "MOSI" at 129.769,7.686 h1.91 r180
  text "GPIO" at 122.657,5.131 h2.03 r180
  text "Function" at 128.543,5.128 h2.03 r180
  text "Circuit" at 140.456,5.131 h2.03 r180
Board Outline:
  lines w0.2: 0.962,26.208 ccw(c-0.876,27.751) 1.524,27.751 ; 0.962,26.208 ccw(c-0.876,27.751) 1.524,27.751 ; 0.962,26.208 0.796,26.042 ccw(c2.717,24.121) 0,24.121 0,1 ccw(c1,1) 1,0 80.3,0 ccw(c80.3,1.18) 81.134,0.346 cw(c81.969,-0.489) 81.969,0.691 90.231,0.691 cw(c90.231,-0.489) 91.066,0.346 ccw(c91.9,1.18) 91.9,0 154,0 ccw(c154,1) 155,1 155,62.5 ccw(c154,62.5) 154,63.5 1,63.5 ccw(c1,62.5) 0,62.5 0,39.381 ccw(c2.717,39.381) 0.796,37.46 0.962,37.294 cw(c-0.876,35.751) 1.524,35.751 ; 1.524,27.751 1.524,35.751 ; 1.524,27.751 1.524,35.751
Top Assembly:
  drawing of 40 lines, arcs and shapes, not listed
Bottom Assembly:
  lines w0.1: 67.94,41.7 67.94,44.8 69.24,44.8 69.24,41.7 67.94,41.7 ; 70.48,41.7 70.48,44.8 71.78,44.8 71.78,41.7 70.48,41.7 ; 73.02,41.7 73.02,44.8 74.32,44.8 74.32,41.7 73.02,41.7 ; 75.56,41.7 75.56,44.8 76.86,44.8 76.86,41.7 75.56,41.7 ; 78.1,41.7 79.4,41.7 79.4,44.8 78.1,44.8 78.1,41.7 ; 80.7,41.7 80.7,44.8 81.9,44.8 81.9,41.7 80.7,41.7
Top Impedance Info:
  lines w0.1: 125.85,20.375 125.85,19.703 ccw(c126.703,19.703) 126.1,19.1 ccw(c127.066,20.066) 127.066,18.7 133.394,18.7 ; 129.225,21.25 129.231,21.256 131.536,21.256 ccw(c131.536,22.85) 133.13,22.85 133.13,28.131 133.13,28.132 133.13,29.195 ; 135.714,18.7 135.72,18.706 136.481,18.706 ccw(c136.481,20.3) 138.074,20.3 138.074,35.207 cw(c138.984,35.207) 138.984,36.117
  text "50 ohm impedance" at 123.19,45.974 h3.05
Top Component Outline:
  pour cut-out: 113.587,64.756 134.329,64.756 134.329,55.804 113.587,55.804
  pour cut-out: 111.349,66.994 136.567,66.994 136.567,53.566 111.349,53.566
  lines w0.125: 113.587,55.804 134.329,55.804 134.329,64.756 113.587,64.756 113.587,55.804

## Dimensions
154,0 to 90.17,55.881 on Dimensions
154,0 to 66.04,40.641 on Dimensions
154,0 to 66.04,12.701 on Dimensions
154,0 to 96.52,7.621 on Dimensions
154,0 to 154,63.5 on Dimensions
0,1 to 96.52,7.621 on Dimensions
0,1 to 66.04,12.701 on Dimensions
0,1 to 15.24,55.881 on Dimensions
0,1 to 13.97,7.621 on Dimensions
0,1 to 155,1 on Dimensions
0,1 to 144.829,63.501 on Dimensions
0,1 to 90.17,55.881 on Dimensions
154,1 to 160.7,-3.566 on Dimensions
